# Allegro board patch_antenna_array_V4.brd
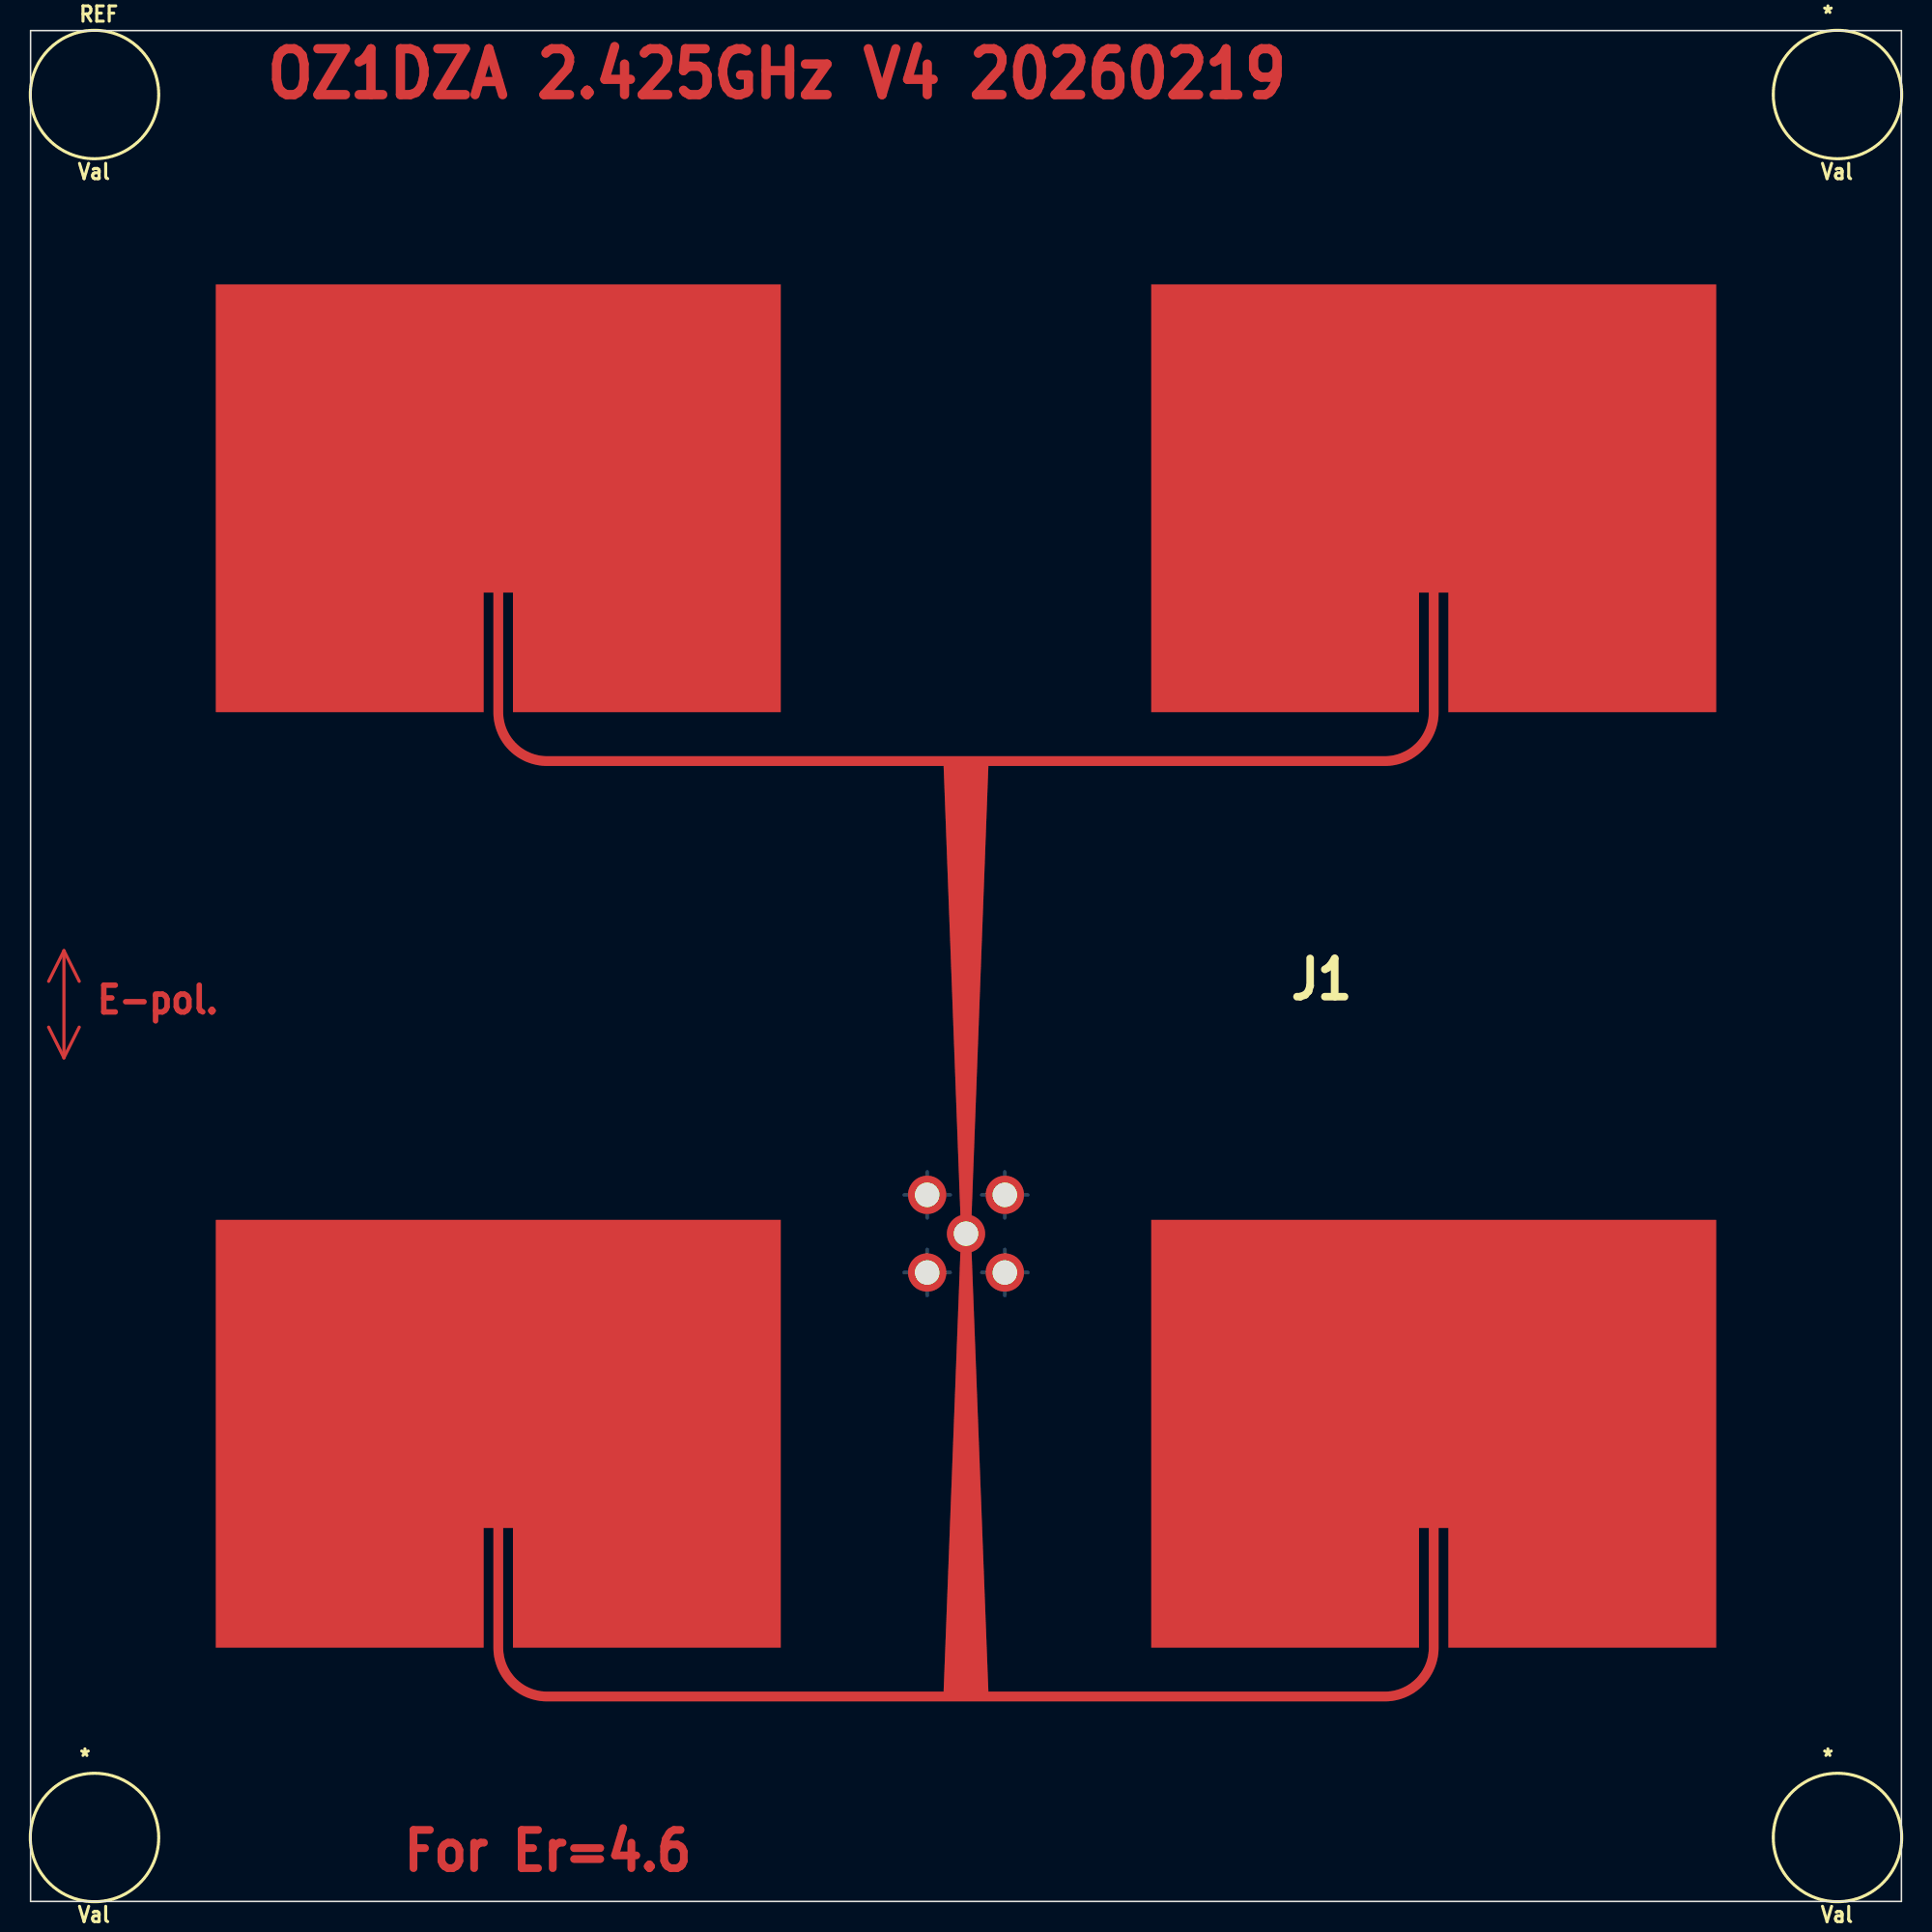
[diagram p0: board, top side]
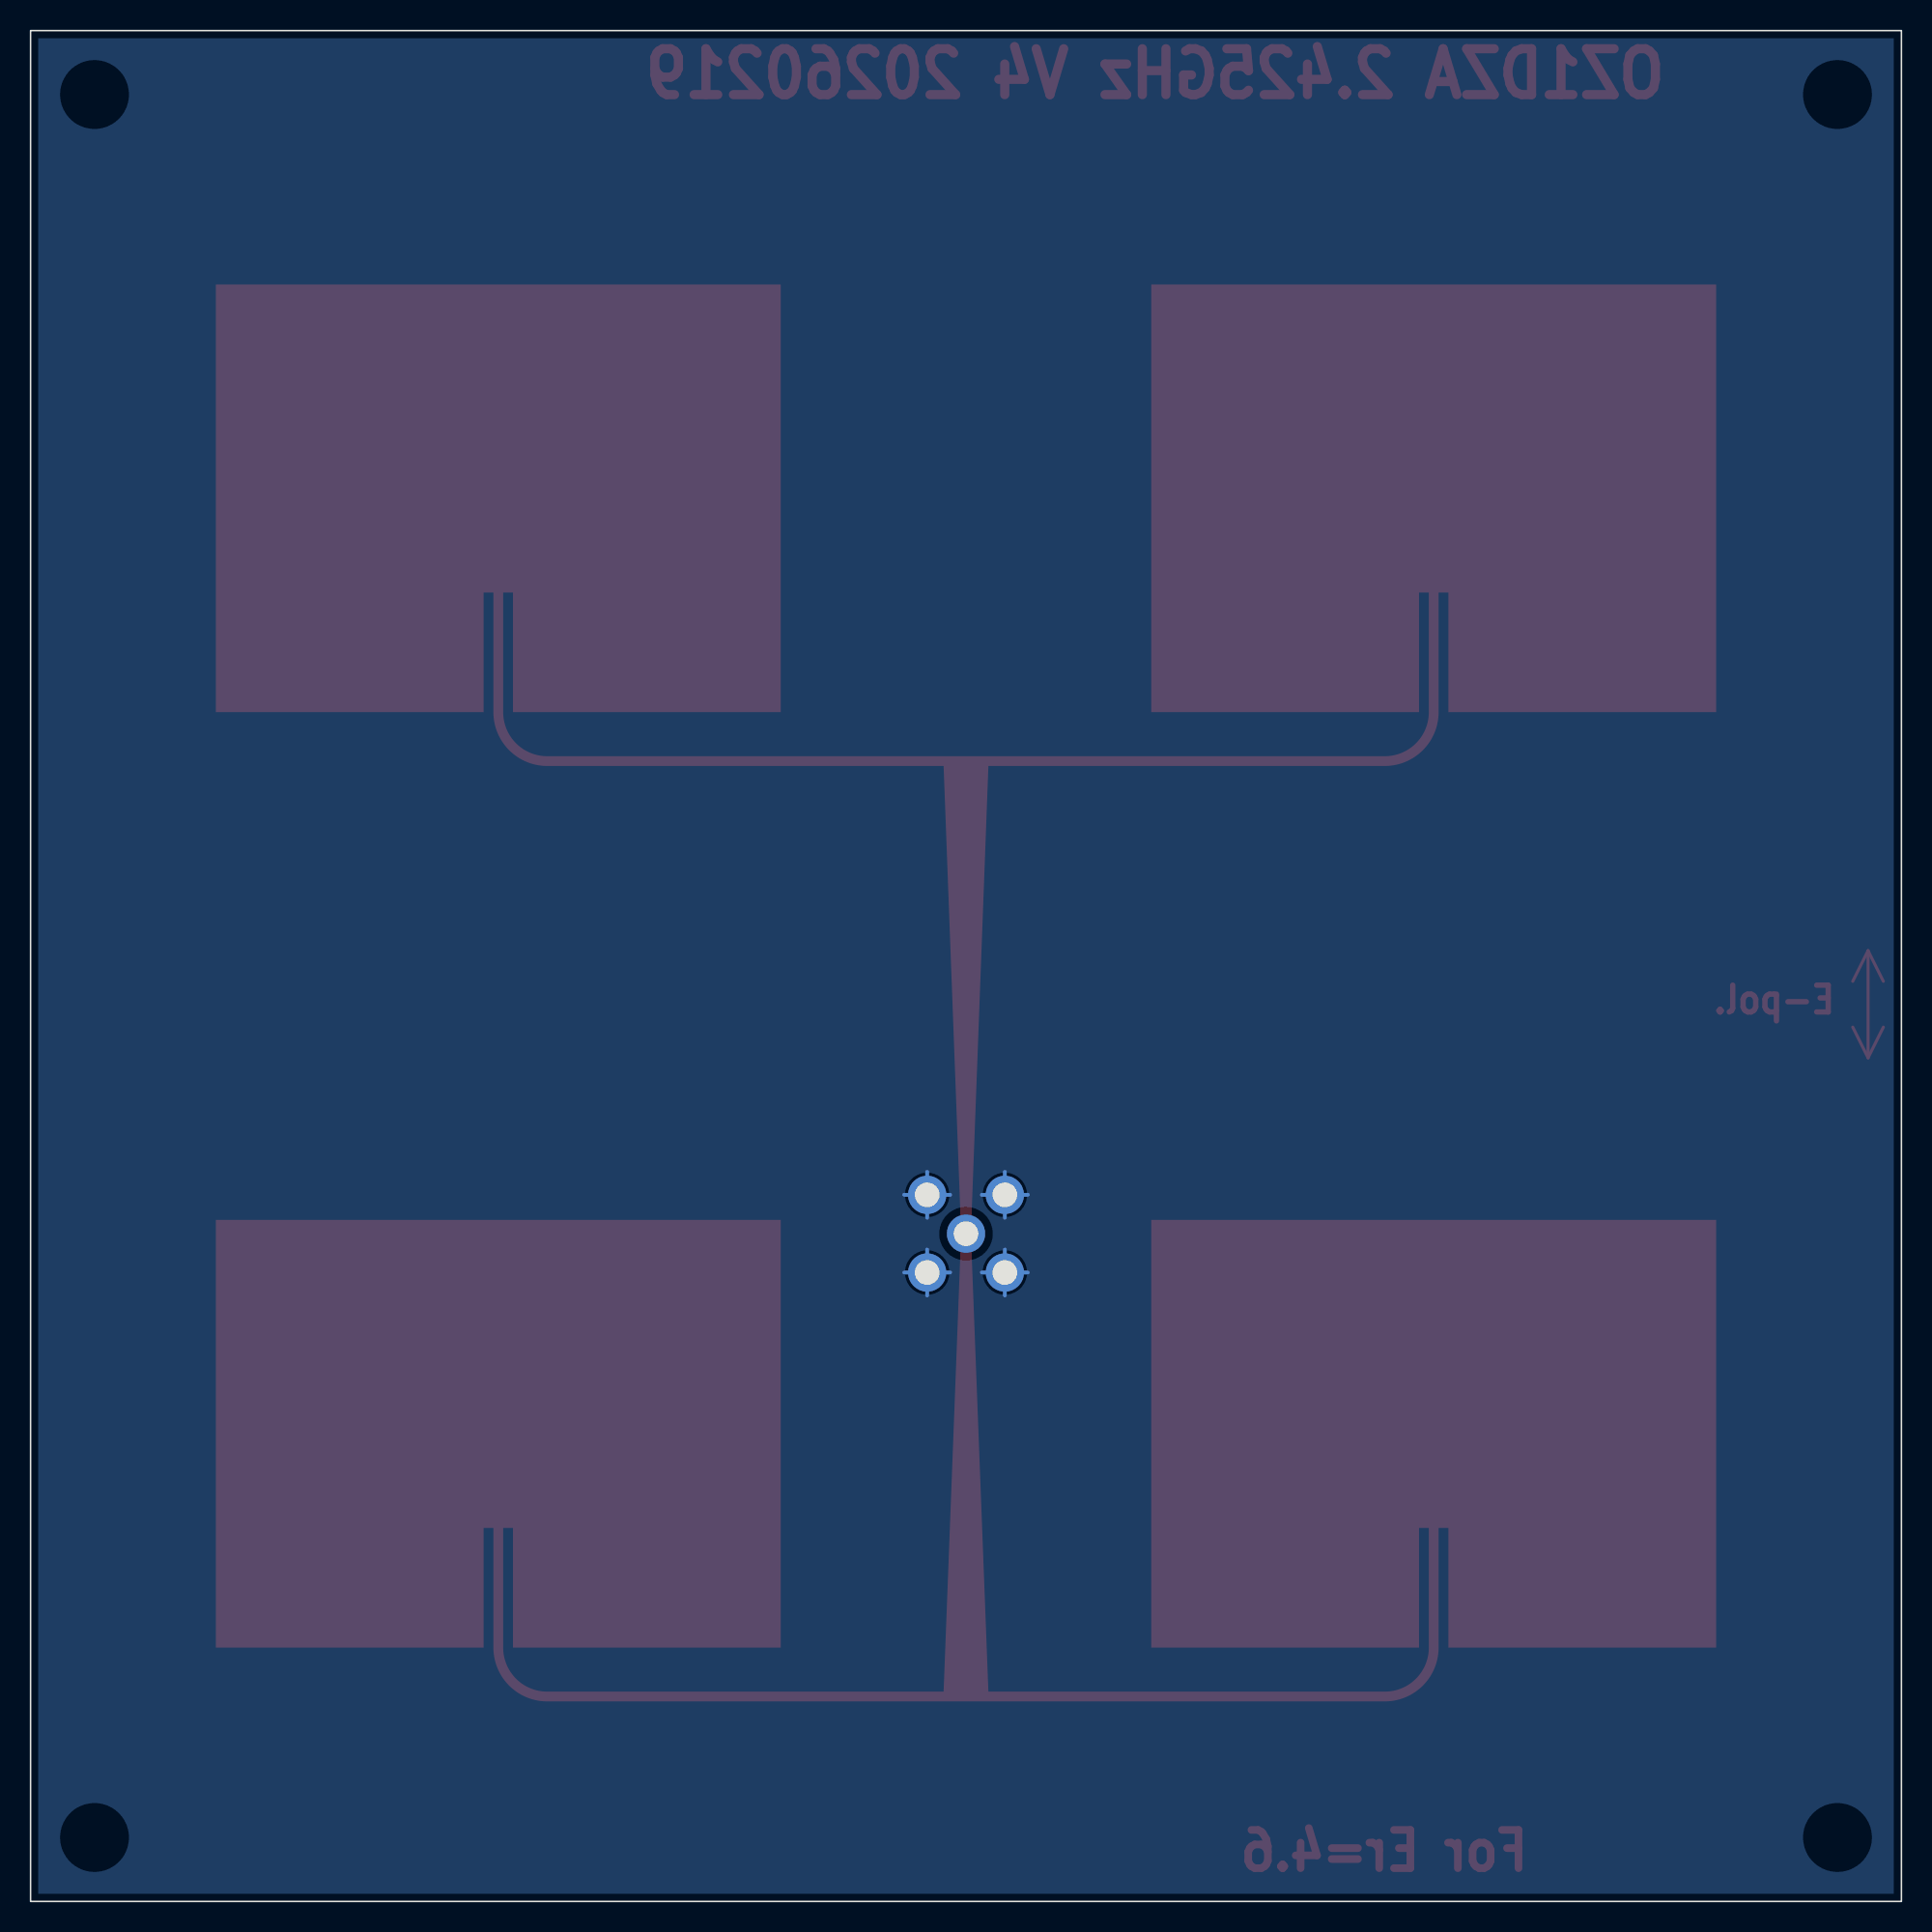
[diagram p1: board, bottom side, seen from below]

Outline 122.36 x 122.36 mm; copper layers: TOP, BOTTOM. Coordinates in mm from the lower left corner of the outline.
Outline path: rectangle 0,0 122.36,122.36

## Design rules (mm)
constraint set DEFAULT: min track width 0.3

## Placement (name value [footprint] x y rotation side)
J1  patch_antenna_array  [PATCH_ANTENNA_ARRAY]  61.18 61.18 0 top
NOREF  -  [#2]  0 0 0 top
NOREF#2  -  [#2]  122.36 0 90 top
REF  Val  [unnamed]  4.18 118.18 0 top
UNK*  Val  [unnamed]  118.18 118.18 0 top
UNK*#2  Val  [unnamed]  4.18 4.18 0 top
UNK*#3  Val  [unnamed]  118.18 4.18 0 top

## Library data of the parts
J1 = CON5

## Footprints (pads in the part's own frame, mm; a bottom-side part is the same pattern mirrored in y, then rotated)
PATCH_ANTENNA_ARRAY
  round 2.5 hole 1.6: 1(0,-17.508) 2(2.54,-14.968) 3(-2.54,-14.968) 4(-2.54,-20.048) 5(2.54,-20.048)
unnamed
  round 0 hole 3.5 unplated: (0,0)

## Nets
GND: J1.2 J1.3 J1.4 J1.5

Pads without a net: J1 1

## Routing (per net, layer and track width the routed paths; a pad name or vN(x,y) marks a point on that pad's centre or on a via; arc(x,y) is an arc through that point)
GND: length 24
  BOTTOM w0.25: J1.5 63.72,42.63 ; J1.5 65.22,41.13 ; J1.5 63.72,39.63 ; J1.5 62.22,41.13 ; 58.64,44.71 J1.3 ; J1.3 60.14,46.21 ; J1.3 58.64,47.71 ; J1.3 57.14,46.21 ; 62.22,46.21 J1.2 ; J1.2 63.72,47.71 ; J1.2 63.72,44.71 ; J1.2 65.22,46.21 ; J1.4 60.14,41.13 ; J1.4 58.64,39.63 ; J1.4 57.14,41.13 ; J1.4 58.64,42.63

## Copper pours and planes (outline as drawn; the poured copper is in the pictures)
GND on BOTTOM: 0,122.36 0,0 122.36,0 122.36,122.36
Net_7 on TOP (solid shape): 49.07,77.78 31.55,77.78 31.55,85.61 30.91,85.61 30.91,77.78 31.75,75.75 33.79,74.91 88.57,74.91 90.61,75.75 91.45,77.78 91.45,85.61 90.81,85.61 90.81,77.78 73.3,77.78 73.3,105.76 110.25,105.76 110.25,77.78 92.73,77.78 92.73,85.61 92.09,85.61 92.09,77.78 91.06,75.3 88.57,74.27 62.65,74.27 61.51,43.99 62.14,43.99 62.14,43.35 61.51,43.35 62.65,13.72 88.57,13.72 90.61,14.57 91.45,16.6 91.45,24.43 90.81,24.43 90.81,16.6 73.3,16.6 73.3,44.58 110.25,44.58 110.25,16.6 92.73,16.6 92.73,24.43 92.09,24.43 92.09,16.6 91.06,14.11 88.57,13.08 33.79,13.08 31.3,14.11 30.27,16.6 30.27,24.43 29.63,24.43 29.63,16.6 12.12,16.6 12.12,44.58 49.07,44.58 49.07,16.6 31.55,16.6 31.55,24.43 30.91,24.43 30.91,16.6 31.75,14.57 33.79,13.72 59.72,13.72 60.86,43.67 59.72,74.27 33.79,74.27 31.3,75.3 30.27,77.78 30.27,85.61 29.63,85.61 29.63,77.78 12.12,77.78 12.12,105.76 49.07,105.76

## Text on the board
TOP: E-pol. | For Er=4.6 | OZ1DZA 2.425GHz V4 20260219
